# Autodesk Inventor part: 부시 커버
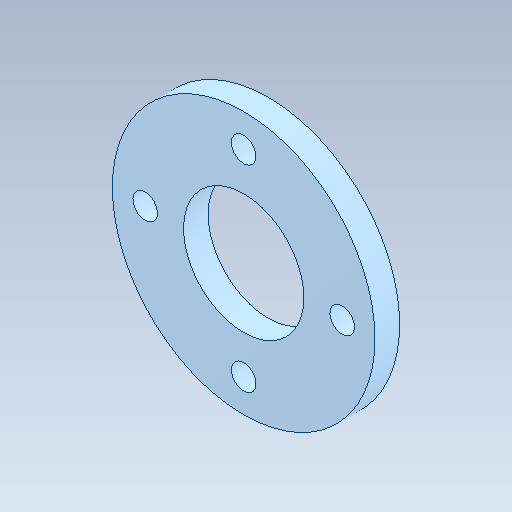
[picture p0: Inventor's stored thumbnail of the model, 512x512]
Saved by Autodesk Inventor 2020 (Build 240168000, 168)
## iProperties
Created: 2024-07
Part Number: 부시 커버
Material: 강철, 연강
Document SubType Name: Modeling
Designer: oem
Density: 7.85 g/cm^3
Appearance: 기본값
Mass: 48.2471 g
Surface Area: 39.7569 cm^2
Volume: 6.14613 cm^3
Sending System: Autodesk Inventor 2025
Preprocessor: ST-DEVELOPER v20
Author: jhkim
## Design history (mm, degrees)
feature "솔리드1"
node "솔리드2"
